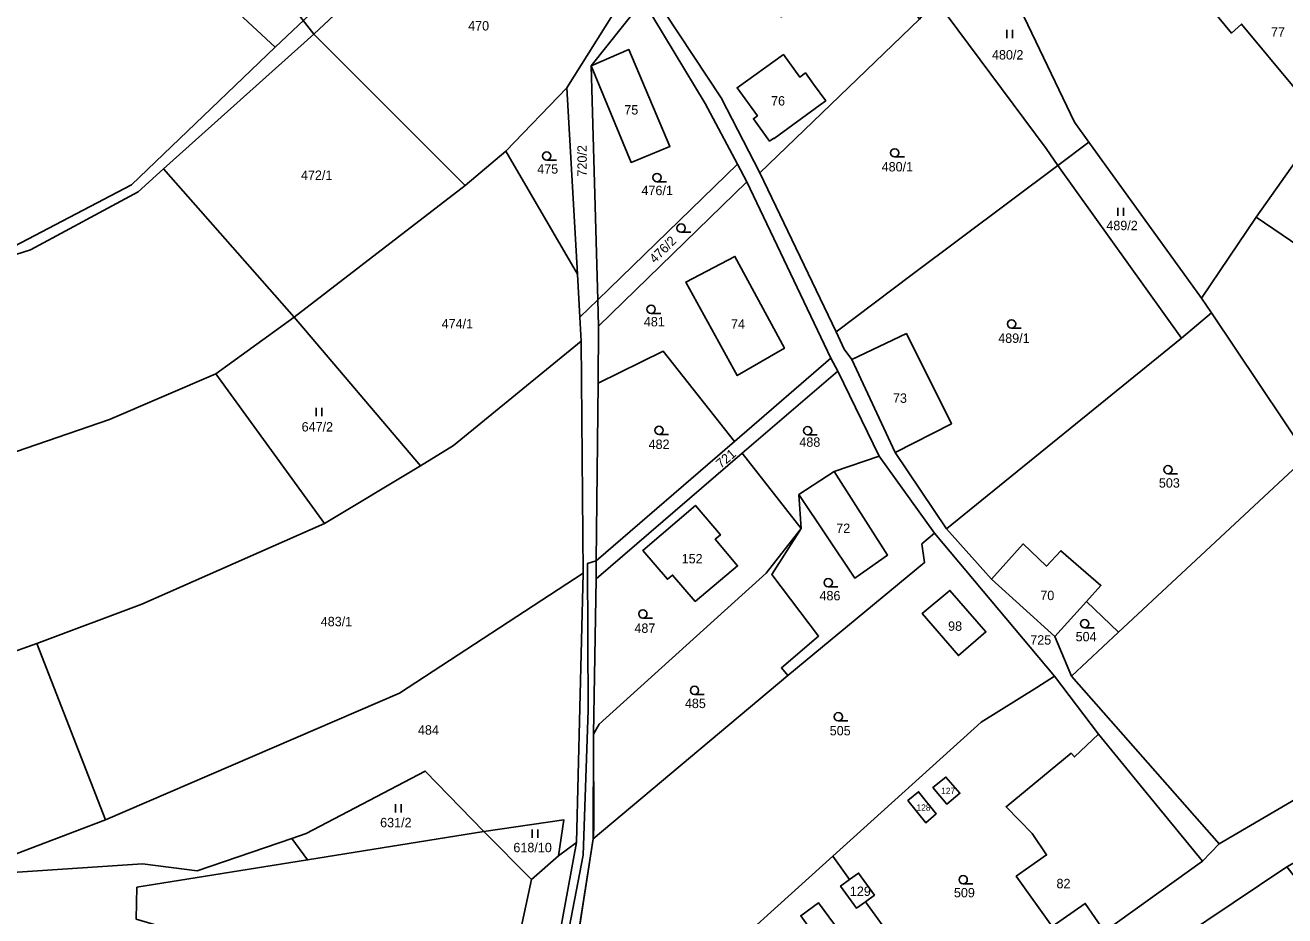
# Model space of a CAD drawing. Extents: x -590606 to -587796, y -1065936 to -1062515.
# Drawn here: x -589641.2 to -589413.2, y -1065080 to -1064918.8 of the extents above; entities that cross this region are included whole.
import ezdxf

# ---------------------------------------------------------------- set-up
doc = ezdxf.new("R2010")
doc.units = 0
for name, color, linetype in [('Cesty', 7, 'Continuous'), ('Parcela nároku', 7, 'Continuous'), ('Vnější obvod_ Studené', 7, 'Continuous'), ('Vrstva 1', 7, 'Continuous'), ('Vrstva 30', 7, 'Continuous'), ('Územní plán', 7, 'Continuous')]:
    doc.layers.add(name, color=color, linetype=linetype)

msp = doc.modelspace()

# ---------------------------------------------------------------- linework, layer by layer
at = {"layer": 'Cesty'}
msp.add_lwpolyline([(-589577.24, -1065198.94), (-589574.86, -1065184.67), (-589568.53, -1065163.67), (-589557.88, -1065137.95), (-589549.66, -1065118.11), (-589544.6, -1065091.93), (-589540.17, -1065069.02), (-589539.27, -1065042.82), (-589539.37, -1065016.25), (-589537.8, -1065015.79)], dxfattribs=at)
at = {"layer": 'Parcela nároku'}
for points in [[(-589672.56, -1064837.8), (-589664.19, -1064828.97), (-589628.67, -1064804.2), (-589550.69, -1064880.06), (-589595.93, -1064922.82), (-589688.26, -1064837.19), (-589677.04, -1064831.33)], [(-589738.8, -1064868.37), (-589722.06, -1064859.86), (-589695.94, -1064842.79), (-589696.42, -1064842.01), (-589688.26, -1064837.19), (-589595.93, -1064922.82), (-589621.92, -1064947.69), (-589643.25, -1064958.89)], [(-589419.51, -1064880.71), (-589429.73, -1064863.35), (-589441.1, -1064876.11), (-589455.18, -1064891.01), (-589467.9, -1064901.87), (-589466.69, -1064904.1), (-589451.25, -1064936.39), (-589448.63, -1064940.01), (-589428.23, -1064968.24), (-589418.35, -1064953.57), (-589406.51, -1064936.87), (-589411.18, -1064930.48), (-589420.99, -1064918.63), (-589422.85, -1064920.26), (-589426.28, -1064916.08), (-589417.57, -1064908.93), (-589404.77, -1064924.29), (-589403.91, -1064923.64), (-589400.68, -1064928.65), (-589394.5, -1064919.94), (-589399.91, -1064912.39), (-589408.85, -1064896.13)], [(-589643.25, -1064958.89), (-589718.4, -1064982.65), (-589738.86, -1064988.82), (-589792.56, -1065010.99), (-589790.16, -1065012.34), (-589739.56, -1064991.1), (-589640.21, -1064959.48), (-589620.7, -1064948.96), (-589616.14, -1064944.82), (-589588.94, -1064920.46), (-589549.47, -1064883.45), (-589550.69, -1064880.06), (-589595.93, -1064922.82), (-589621.92, -1064947.69)], [(-589531.78, -1064912.02), (-589537.45, -1064904.41), (-589545.23, -1064888.95), (-589549.47, -1064883.45), (-589588.94, -1064920.46), (-589561.54, -1064947.84), (-589554.15, -1064941.61), (-589543.1, -1064930.15), (-589532.21, -1064912.7)], [(-589479.31, -1064917.7), (-589490.4, -1064901.33), (-589504.34, -1064917.35), (-589517.52, -1064904.58), (-589527.95, -1064912.63), (-589515.22, -1064931.98), (-589508.2, -1064945.52)], [(-589448.63, -1064940.01), (-589451.25, -1064936.39), (-589466.69, -1064904.1), (-589476.4, -1064914.15), (-589456.4, -1064941.16), (-589454.23, -1064944.2)], [(-589403.91, -1064923.64), (-589404.77, -1064924.29), (-589417.57, -1064908.93), (-589426.28, -1064916.08), (-589422.85, -1064920.26), (-589420.99, -1064918.63), (-589411.18, -1064930.48), (-589406.51, -1064936.87), (-589400.68, -1064928.65)], [(-589538.71, -1064926.19), (-589537.53, -1064968.54), (-589540.75, -1064971.67), (-589541.18, -1064963.89), (-589543.1, -1064930.15), (-589532.21, -1064912.7), (-589530.19, -1064915.51)], [(-589451.81, -1065036.64), (-589454.82, -1065029.46), (-589466.26, -1065019.11), (-589474.4, -1065009.98), (-589483.68, -1064996.15), (-589491.55, -1064979.3), (-589492.91, -1064977.48), (-589494.4, -1064974.29), (-589508.2, -1064945.52), (-589515.22, -1064931.98), (-589527.95, -1064912.63), (-589529.31, -1064914.41), (-589518.09, -1064932.98), (-589512.24, -1064943.97), (-589510.53, -1064947.19), (-589495.32, -1064979.07), (-589494.1, -1064981.46), (-589486.57, -1064996.85), (-589476.59, -1065010.77), (-589454.84, -1065036.64), (-589446.88, -1065047.17), (-589438.79, -1065057.06), (-589428.09, -1065070.14), (-589425.07, -1065067.02)], [(-589479.31, -1064917.7), (-589508.2, -1064945.52), (-589494.4, -1064974.29), (-589480.65, -1064963.95), (-589454.23, -1064944.2), (-589456.4, -1064941.16), (-589476.4, -1064914.15)], [(-589588.94, -1064920.46), (-589561.54, -1064947.84), (-589592.46, -1064971.67), (-589616.14, -1064944.82)], [(-589396.04, -1064941.45), (-589398.25, -1064938.99), (-589387.73, -1064929), (-589394.5, -1064919.94), (-589400.68, -1064928.65), (-589406.51, -1064936.87), (-589418.35, -1064953.57), (-589383.75, -1064977.12), (-589379.59, -1064969.17), (-589368.16, -1064947.4), (-589379.39, -1064938.24), (-589392.85, -1064951.99), (-589399.41, -1064944.5)], [(-589538.71, -1064926.19), (-589531.9, -1064923.24), (-589524.48, -1064940.76), (-589531.49, -1064943.65)], [(-589500.97, -1064928.2), (-589499.94, -1064927.45), (-589498.46, -1064929.48), (-589496.26, -1064932.49), (-589497.29, -1064933.25), (-589505.63, -1064939.35), (-589505.69, -1064939.27), (-589506.43, -1064939.8), (-589509.37, -1064935.76), (-589508.63, -1064935.22), (-589512.32, -1064930.15), (-589503.92, -1064924.15)], [(-589497.29, -1064933.25), (-589505.63, -1064939.35), (-589505.69, -1064939.27), (-589506.43, -1064939.8), (-589509.37, -1064935.76), (-589508.63, -1064935.22), (-589512.32, -1064930.15), (-589503.92, -1064924.15), (-589500.97, -1064928.2), (-589499.94, -1064927.45), (-589498.46, -1064929.48), (-589496.26, -1064932.49)], [(-589554.15, -1064941.61), (-589543.1, -1064930.15), (-589541.18, -1064963.89)], [(-589554.15, -1064941.61), (-589561.54, -1064947.84), (-589592.46, -1064971.67), (-589569.59, -1064998.55), (-589563.66, -1064994.88), (-589540.51, -1064976.01), (-589540.75, -1064971.67), (-589541.18, -1064963.89)], [(-589428.23, -1064968.24), (-589448.63, -1064940.01), (-589454.23, -1064944.2), (-589431.86, -1064975.44), (-589426.46, -1064970.88)], [(-589739.56, -1064991.1), (-589640.21, -1064959.48), (-589620.7, -1064948.96), (-589616.14, -1064944.82), (-589592.46, -1064971.67), (-589606.65, -1064981.94), (-589625.91, -1064990.19), (-589721.56, -1065023.05), (-589759.46, -1065038.64), (-589790.16, -1065012.34)], [(-589537.53, -1064968.54), (-589512.24, -1064943.97), (-589510.53, -1064947.19), (-589537.4, -1064973.3)], [(-589473.53, -1064990.97), (-589483.68, -1064996.15), (-589474.4, -1065009.98), (-589431.86, -1064975.44), (-589454.23, -1064944.2), (-589480.65, -1064963.95), (-589494.4, -1064974.29), (-589492.91, -1064977.48), (-589491.55, -1064979.3), (-589481.66, -1064974.63)], [(-589537.4, -1064973.3), (-589537.45, -1064983.64), (-589525.7, -1064977.8), (-589512.79, -1064994.19), (-589495.32, -1064979.07), (-589510.53, -1064947.19)], [(-589418.35, -1064953.57), (-589383.75, -1064977.12), (-589399.02, -1065006.32), (-589409.1, -1064996.85), (-589426.46, -1064970.88), (-589428.23, -1064968.24)], [(-589512.7, -1064960.66), (-589503.76, -1064977.28), (-589512.28, -1064982.25), (-589521.6, -1064965.3)], [(-589512.28, -1064982.25), (-589521.6, -1064965.3), (-589512.7, -1064960.66), (-589503.76, -1064977.28)], [(-589577.57, -1065190.24), (-589549.86, -1065113.03), (-589541.38, -1065066.73), (-589540.15, -1065017.98), (-589540.51, -1064976.01), (-589540.75, -1064971.67), (-589537.53, -1064968.54), (-589537.4, -1064973.3), (-589537.45, -1064983.64), (-589537.8, -1065015.79), (-589537.8, -1065019.01), (-589538.32, -1065047.17), (-589538.25, -1065064.22), (-589538.37, -1065066.07), (-589542.82, -1065094.63), (-589547.12, -1065116.37), (-589572.74, -1065186.9)], [(-589409.1, -1064996.85), (-589426.46, -1064970.88), (-589431.86, -1064975.44), (-589474.4, -1065009.98), (-589466.26, -1065019.11), (-589460.55, -1065012.72), (-589456.29, -1065016.72), (-589453.72, -1065013.94), (-589446.47, -1065020.23), (-589449.1, -1065023.14), (-589443.26, -1065028.68)], [(-589606.65, -1064981.94), (-589592.46, -1064971.67), (-589569.59, -1064998.55), (-589586.97, -1065009.02)], [(-589491.55, -1064979.3), (-589481.66, -1064974.63), (-589473.53, -1064990.97), (-589483.68, -1064996.15)], [(-589569.59, -1064998.55), (-589586.97, -1065009.02), (-589620.06, -1065023.62), (-589639.08, -1065030.72), (-589626.65, -1065062.62), (-589573.43, -1065039.74), (-589540.15, -1065017.98), (-589540.51, -1064976.01), (-589563.66, -1064994.88)], [(-589537.8, -1065015.79), (-589537.45, -1064983.64), (-589525.7, -1064977.8), (-589512.79, -1064994.19)], [(-589537.8, -1065019.01), (-589537.8, -1065015.79), (-589512.79, -1064994.19), (-589495.32, -1064979.07), (-589494.1, -1064981.46), (-589511.37, -1064996.26)], [(-589625.91, -1064990.19), (-589606.65, -1064981.94), (-589586.97, -1065009.02), (-589620.06, -1065023.62), (-589639.08, -1065030.72), (-589689.01, -1065048.5), (-589721.56, -1065023.05)], [(-589494.1, -1064981.46), (-589511.37, -1064996.26), (-589500.73, -1065009.92), (-589501.12, -1065003.77), (-589494.75, -1064999.6), (-589486.57, -1064996.85)], [(-589538.32, -1065047.17), (-589537.8, -1065019.01), (-589511.37, -1064996.26), (-589500.73, -1065009.92), (-589507.06, -1065018.02), (-589537.27, -1065045.33)], [(-589497.57, -1065029.38), (-589504.29, -1065035.14), (-589503.15, -1065036.55), (-589478.37, -1065016.09), (-589478.86, -1065012.72), (-589476.59, -1065010.77), (-589486.57, -1064996.85), (-589494.75, -1064999.6), (-589485.06, -1065014.72), (-589491.02, -1065018.9), (-589501.12, -1065003.77), (-589500.73, -1065009.92), (-589506.02, -1065018.24)], [(-589399.02, -1065006.32), (-589409.1, -1064996.85), (-589443.26, -1065028.68), (-589451.81, -1065036.64), (-589425.07, -1065067.02), (-589381.58, -1065041.51), (-589371.02, -1065032.81)], [(-589494.75, -1064999.6), (-589485.06, -1065014.72), (-589491.02, -1065018.9), (-589501.12, -1065003.77)], [(-589515.34, -1065011.07), (-589516.27, -1065011.86), (-589512.23, -1065016.68), (-589519.88, -1065023.12), (-589523.99, -1065018.34), (-589524.91, -1065019.11), (-589529.37, -1065013.87), (-589519.85, -1065005.75)], [(-589516.27, -1065011.86), (-589512.23, -1065016.68), (-589519.88, -1065023.12), (-589523.99, -1065018.34), (-589524.91, -1065019.11), (-589529.37, -1065013.87), (-589519.85, -1065005.75), (-589515.34, -1065011.07)], [(-589537.27, -1065045.33), (-589538.32, -1065047.17), (-589538.25, -1065064.22), (-589538.37, -1065066.07), (-589503.15, -1065036.55), (-589504.29, -1065035.14), (-589497.57, -1065029.38), (-589506.02, -1065018.24), (-589500.73, -1065009.92), (-589507.06, -1065018.02)], [(-589478.37, -1065016.09), (-589503.15, -1065036.55), (-589538.37, -1065066.07), (-589542.82, -1065094.63), (-589547.12, -1065116.37), (-589543.73, -1065113.31), (-589522.14, -1065093.79), (-589504.94, -1065078.24), (-589494.98, -1065069.24), (-589468.15, -1065044.98), (-589458.09, -1065038.68), (-589454.84, -1065036.64), (-589476.59, -1065010.77), (-589478.86, -1065012.72)], [(-589453.72, -1065013.94), (-589446.47, -1065020.23), (-589449.1, -1065023.14), (-589454.82, -1065029.46), (-589466.26, -1065019.11), (-589460.55, -1065012.72), (-589456.29, -1065016.72)], [(-589540.15, -1065017.98), (-589573.43, -1065039.74), (-589626.65, -1065062.62), (-589653.49, -1065072.84), (-589619.91, -1065070.61), (-589610.04, -1065071.9), (-589592.92, -1065066.04), (-589590.3, -1065065.14), (-589568.75, -1065053.81), (-589558.18, -1065064.74), (-589543.69, -1065062.64), (-589544.64, -1065069.18), (-589541.38, -1065066.73)], [(-589478.82, -1065025.33), (-589473.78, -1065021.13), (-589467.28, -1065028.64), (-589472.24, -1065032.93)], [(-589472.24, -1065032.93), (-589478.82, -1065025.33), (-589473.78, -1065021.13), (-589467.28, -1065028.64)], [(-589449.1, -1065023.14), (-589454.82, -1065029.46), (-589451.81, -1065036.64), (-589443.26, -1065028.68)], [(-589639.08, -1065030.72), (-589626.65, -1065062.62), (-589653.49, -1065072.84), (-589672.93, -1065073.61), (-589697.05, -1065065.15), (-589725.64, -1065065.8), (-589729.74, -1065062.5), (-589689.01, -1065048.5)], [(-589454.84, -1065036.64), (-589446.88, -1065047.17), (-589451.25, -1065051.25), (-589451.84, -1065050.59), (-589463.64, -1065060.28), (-589458.93, -1065065.12), (-589456.3, -1065069), (-589461.79, -1065072.85), (-589455.31, -1065081.93), (-589449.3, -1065077.79), (-589445.82, -1065082.83), (-589454.83, -1065089.29), (-589458.35, -1065084.21), (-589475.58, -1065096.14), (-589489.05, -1065077.46), (-589487.45, -1065076.26), (-589490.33, -1065072.29), (-589491.94, -1065073.46), (-589494.98, -1065069.24), (-589468.15, -1065044.98), (-589458.09, -1065038.68)], [(-589438.79, -1065057.06), (-589428.09, -1065070.14), (-589445.82, -1065082.83), (-589449.3, -1065077.79), (-589455.31, -1065081.93), (-589461.79, -1065072.85), (-589456.3, -1065069), (-589458.93, -1065065.12), (-589463.64, -1065060.28), (-589451.84, -1065050.59), (-589451.25, -1065051.25), (-589446.88, -1065047.17)], [(-589592.92, -1065066.04), (-589590.3, -1065065.14), (-589568.75, -1065053.81), (-589558.18, -1065064.74), (-589590.05, -1065069.91)], [(-589474.53, -1065054.9), (-589471.99, -1065057.85), (-589474.36, -1065059.8), (-589476.88, -1065056.8)], [(-589474.36, -1065059.8), (-589476.88, -1065056.8), (-589474.53, -1065054.9), (-589471.99, -1065057.85)], [(-589479.46, -1065057.55), (-589481.4, -1065059.15), (-589478.15, -1065063.22), (-589476.26, -1065061.54)], [(-589478.15, -1065063.22), (-589476.26, -1065061.54), (-589479.46, -1065057.55), (-589481.4, -1065059.15)], [(-589558.18, -1065064.74), (-589590.05, -1065069.91), (-589620.93, -1065074.85), (-589621.05, -1065080.6), (-589607.58, -1065084.63), (-589606.55, -1065096.67), (-589562.34, -1065112.16), (-589554.67, -1065097.26), (-589549.52, -1065073.43)], [(-589558.18, -1065064.74), (-589543.69, -1065062.64), (-589544.64, -1065069.18), (-589549.52, -1065073.43)], [(-589607.56, -1065184.27), (-589613.92, -1065188.4), (-589617.61, -1065203.04), (-589611.87, -1065223.17), (-589592.7, -1065199.64), (-589577.57, -1065190.24), (-589549.86, -1065113.03), (-589541.38, -1065066.73), (-589544.64, -1065069.18), (-589549.52, -1065073.43), (-589554.67, -1065097.26), (-589562.34, -1065112.16), (-589572.76, -1065131.63), (-589583.57, -1065163.54)], [(-589504.94, -1065078.24), (-589494.98, -1065069.24), (-589491.94, -1065073.46), (-589493.57, -1065074.64), (-589490.67, -1065078.66), (-589489.05, -1065077.46), (-589475.58, -1065096.14), (-589458.35, -1065084.21), (-589454.83, -1065089.29), (-589471.77, -1065101.42), (-589491.61, -1065118.9), (-589527.75, -1065151), (-589531.71, -1065154.52), (-589546.14, -1065118.8), (-589547.12, -1065116.37), (-589543.73, -1065113.31), (-589522.14, -1065093.79)], [(-589389.87, -1065100.03), (-589412.82, -1065071.17), (-589432.22, -1065084.17), (-589431.18, -1065086.73), (-589428.43, -1065092.41), (-589422.14, -1065099.19), (-589378.86, -1065152.89), (-589352.63, -1065182.93), (-589324.71, -1065146.34), (-589373.33, -1065088.79)], [(-589490.33, -1065072.29), (-589491.94, -1065073.46), (-589493.57, -1065074.64), (-589490.67, -1065078.66), (-589489.05, -1065077.46), (-589487.45, -1065076.26)], [(-589497.6, -1065077.66), (-589500.8, -1065080.02), (-589497.91, -1065083.98), (-589494.71, -1065081.59)], [(-589497.91, -1065083.98), (-589494.71, -1065081.59), (-589497.6, -1065077.66), (-589500.8, -1065080.02)]]:
    msp.add_lwpolyline(points, close=True, dxfattribs=at)
for points in [[(-589432.22, -1065084.17), (-589412.82, -1065071.17), (-589396, -1065061.67), (-589375.89, -1065050.78), (-589366.54, -1065042.39), (-589342.09, -1065021.3), (-589327.88, -1064990.45), (-589316.85, -1064962.35), (-589313.53, -1064953.98), (-589300.67, -1064925.35), (-589308.87, -1064919.53), (-589315.72, -1064936.94), (-589319.44, -1064942.57), (-589322.86, -1064951.87), (-589332.39, -1064977.16), (-589334.15, -1064981.25), (-589345.5, -1065006.58), (-589350.89, -1065013.72), (-589371.02, -1065032.81), (-589381.58, -1065041.51), (-589425.07, -1065067.02), (-589428.09, -1065070.14), (-589445.82, -1065082.83)], [(-589717.32, -1065085.65), (-589731.97, -1065078.6), (-589747.98, -1065071.62), (-589756.67, -1065059.05), (-589771, -1065049.48), (-589784.67, -1065037.04), (-589802.07, -1065023.73), (-589795.76, -1065017.7), (-589790.16, -1065012.34), (-589759.46, -1065038.64), (-589729.74, -1065062.5), (-589725.64, -1065065.8), (-589697.05, -1065065.15), (-589672.93, -1065073.61), (-589653.49, -1065072.84), (-589619.91, -1065070.61), (-589610.04, -1065071.9), (-589592.92, -1065066.04), (-589590.05, -1065069.91), (-589620.93, -1065074.85), (-589621.05, -1065080.6)]]:
    msp.add_lwpolyline(points, dxfattribs=at)
at = {"layer": 'Vnější obvod_ Studené'}
for p, q in [((-589588.94, -1064920.46), (-589549.47, -1064883.45)), ((-589616.14, -1064944.82), (-589588.94, -1064920.46)), ((-589592.46, -1064971.67), (-589616.14, -1064944.82)), ((-589537.53, -1064968.54), (-589540.75, -1064971.67)), ((-589537.4, -1064973.3), (-589537.53, -1064968.54)), ((-589569.59, -1064998.55), (-589592.46, -1064971.67)), ((-589540.75, -1064971.67), (-589540.51, -1064976.01)), ((-589537.45, -1064983.64), (-589537.4, -1064973.3)), ((-589540.51, -1064976.01), (-589563.66, -1064994.88)), ((-589537.8, -1065015.79), (-589537.45, -1064983.64)), ((-589563.66, -1064994.88), (-589569.59, -1064998.55)), ((-589537.8, -1065019.01), (-589537.8, -1065015.79)), ((-589538.32, -1065047.17), (-589537.8, -1065019.01)), ((-589538.37, -1065066.07), (-589538.32, -1065047.17)), ((-589542.82, -1065094.63), (-589538.37, -1065066.07))]:
    msp.add_line(p, q, dxfattribs=at)
at = {"layer": 'Vrstva 1'}
for points in [[(-589538.71, -1064926.19), (-589530.19, -1064915.51), (-589529.31, -1064914.41), (-589518.09, -1064932.98), (-589512.24, -1064943.97), (-589537.53, -1064968.54)], [(-589538.71, -1064926.19), (-589531.49, -1064943.65), (-589524.48, -1064940.76), (-589531.9, -1064923.24)]]:
    msp.add_lwpolyline(points, close=True, dxfattribs=at)
at = {"layer": 'Vrstva 30'}
for p, q in [((-589463.46, -1064919.64), (-589463.46, -1064921.14)), ((-589462.44, -1064921.14), (-589462.44, -1064919.64)), ((-589545.02, -1064943.24), (-589546.77, -1064943.24)), ((-589482.03, -1064942.67), (-589483.78, -1064942.67)), ((-589525.06, -1064947.14), (-589526.81, -1064947.14)), ((-589443.41, -1064951.85), (-589443.41, -1064953.35)), ((-589442.39, -1064953.35), (-589442.39, -1064951.85)), ((-589520.7, -1064956.3), (-589522.45, -1064956.3)), ((-589526.13, -1064970.99), (-589527.88, -1064970.99)), ((-589460.89, -1064973.64), (-589462.64, -1064973.64)), ((-589588.51, -1064988.09), (-589588.51, -1064989.59)), ((-589587.48, -1064989.59), (-589587.48, -1064988.09)), ((-589524.7, -1064992.9), (-589526.45, -1064992.9)), ((-589497.8, -1064992.96), (-589499.55, -1064992.96)), ((-589432.58, -1065000.01), (-589434.33, -1065000.01)), ((-589494.07, -1065020.47), (-589495.82, -1065020.47)), ((-589527.62, -1065026.13), (-589529.37, -1065026.13)), ((-589447.66, -1065027.89), (-589449.41, -1065027.89)), ((-589518.27, -1065039.97), (-589520.02, -1065039.97)), ((-589492.25, -1065044.74), (-589494, -1065044.74)), ((-589574.12, -1065059.8), (-589574.12, -1065061.3)), ((-589573.09, -1065061.3), (-589573.09, -1065059.8)), ((-589549.42, -1065064.4), (-589549.42, -1065065.9)), ((-589548.4, -1065065.9), (-589548.4, -1065064.4)), ((-589469.64, -1065074.23), (-589471.39, -1065074.23))]:
    msp.add_line(p, q, dxfattribs=at)
for centre in [(-589483.78, -1064941.92), (-589546.77, -1064942.49), (-589526.81, -1064946.39), (-589522.45, -1064955.55), (-589527.88, -1064970.24), (-589462.64, -1064972.89), (-589526.45, -1064992.15), (-589499.55, -1064992.21), (-589434.33, -1064999.26), (-589495.82, -1065019.72), (-589529.37, -1065025.38), (-589449.41, -1065027.14), (-589520.02, -1065039.22), (-589494, -1065043.99), (-589471.39, -1065073.48)]:
    msp.add_circle(centre, 0.75, dxfattribs=at)
at = {"layer": 'Územní plán'}
msp.add_line((-589664.99, -1064821.89), (-589588.94, -1064920.46), dxfattribs=at)

# ---------------------------------------------------------------- texts
at = {"layer": 'Parcela nároku'}
for s, height, p in [('470', 1.7, (-589560.99, -1064919.78)), ('77', 1.7, (-589415.69, -1064920.91)), ('480/2', 1.7, (-589466.18, -1064925.03)), ('76', 1.7, (-589506.16, -1064933.36)), ('75', 1.7, (-589532.73, -1064934.99)), ('480/1', 1.7, (-589486.15, -1064945.29)), ('472/1', 1.7, (-589591.25, -1064946.82)), ('475', 1.7, (-589548.49, -1064945.69)), ('476/1', 1.7, (-589529.62, -1064949.58)), ('489/2', 1.7, (-589445.48, -1064955.92)), ('474/1', 1.7, (-589565.79, -1064973.71)), ('481', 1.7, (-589529.19, -1064973.33)), ('74', 1.7, (-589513.42, -1064973.76)), ('489/1', 1.7, (-589465.05, -1064976.32)), ('73', 1.7, (-589484.1, -1064987.17)), ('647/2', 1.7, (-589591.13, -1064992.36)), ('482', 1.7, (-589528.33, -1064995.52)), ('488', 1.7, (-589501.04, -1064995.12)), ('503', 1.7, (-589435.97, -1065002.52)), ('72', 1.7, (-589494.37, -1065010.73)), ('152', 1.7, (-589522.35, -1065016.23)), ('486', 1.7, (-589497.4, -1065022.92)), ('70', 1.7, (-589457.43, -1065022.88)), ('483/1', 1.7, (-589587.67, -1065027.61)), ('487', 1.7, (-589530.9, -1065028.81)), ('98', 1.7, (-589474.12, -1065028.43)), ('725', 1.7, (-589459.25, -1065030.93)), ('504', 1.7, (-589451.04, -1065030.34)), ('485', 1.7, (-589521.76, -1065042.42)), ('484', 1.7, (-589570.08, -1065047.23)), ('505', 1.7, (-589495.55, -1065047.36)), ('127', 1.14, (-589475.38, -1065057.98)), ('128', 1.14, (-589479.84, -1065061)), ('631/2', 1.7, (-589576.92, -1065063.99)), ('618/10', 1.7, (-589552.8, -1065068.51)), ('82', 1.7, (-589454.5, -1065075.03)), ('129', 1.7, (-589491.9, -1065076.43)), ('509', 1.7, (-589473.07, -1065076.68))]:
    msp.add_text(s, height=height, dxfattribs=at).set_placement(p)
for s, rotation, p in [('720/2', 90, (-589539.51, -1064946.21)), ('476/2', 45, (-589527.18, -1064962.04)), ('721', 40.3141, (-589515.24, -1064999.12))]:
    msp.add_text(s, height=1.7, rotation=rotation, dxfattribs=at).set_placement(p)

doc.saveas('drawing.dxf')
